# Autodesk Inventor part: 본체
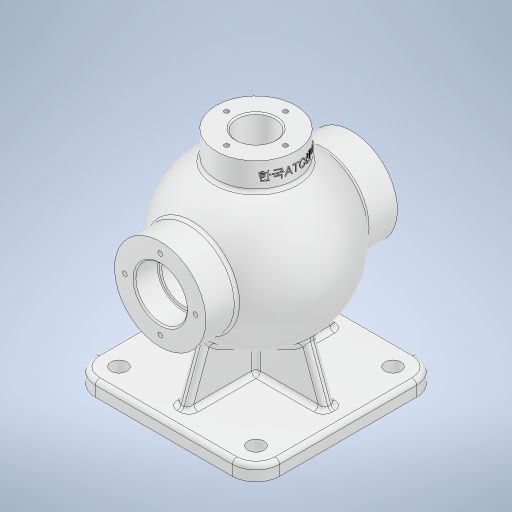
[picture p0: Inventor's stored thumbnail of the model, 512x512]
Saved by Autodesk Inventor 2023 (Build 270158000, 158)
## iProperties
Created: 2023-07
Part Number: 본체
Material: 알루미늄 6061
Document SubType Name: Modeling
Designer: Owner
Density: 2.7 g/cm^3
Appearance: 알루미늄 - 평지
Mass: 1526.72 g
Surface Area: 1173.82 cm^2
Volume: 565.453 cm^3
Author: Owner
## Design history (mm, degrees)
sketch "스케치1"
  geometry: L1 (62.5, 62.5)-(-62.5, 62.5); L2 (-62.5, 62.5)-(-62.5, -62.5); L3 (-62.5, -62.5)-(62.5, -62.5); L4 (62.5, -62.5)-(62.5, 62.5); L5 (62.5, 62.5)-(-62.5, -62.5); L6 (-62.5, 62.5)-(62.5, -62.5); 1 further point
  constraints: 12 end point, 2 midpoint, 2 parallel, 1 horizontal, 1 perpendicular
  dimensions: "d0" = 125 distance of L3.end L2.end; "d1" = 125 distance of L2.end L1.end
extrude "돌출1" new body sketch "스케치1" distance "d2" = 10; taper "d3" = 0 deg
sketch "스케치2"
  geometry: L1 (85, 65)-(85, -65); L2 (0, -62.5)-(0, 62.5) reference; L3 (85, 65)-(54, 65); L4 (54, -65)-(85, -65); L5 (54, 65)-(54, 44.215); L6 (54, -44.215)-(54, -65); A1 r 54 centre (85, 0) between (54, 44.215) and (54, -44.215); 8 further points
  constraints: 10 end point, 4 horizontal alignment, 3 vertical, 2 horizontal, 2 midpoint, 2 point on circle, 1 centre point, 1 coincident, 1 collinear, 6 other
  dimensions: "d5" = 85 distance between parallel lines of L2 L1; "d8" = 130 distance between parallel lines of L4 L3; "d11" = 31 distance of L1.start L3.end; "d12" = 54 radius of A1
revolve "회전1" sketch "스케치2" stored, may be unused: angle "d13" = 90 deg
sketch "스케치3"
  geometry: L1 (10, 50.5)-(85, 23.202); L2 (85, 23.202)-(85, -23.202); L3 (85, -23.202)-(10, -50.5); L4 (10, -62.5)-(10, 62.5) reference; L5 (0, -62.5)-(0, 62.5) reference; L6 (0, -62.5)-(10, -62.5) reference; L7 (0, 62.5)-(10, 62.5) reference; 1 further point
  constraints: 6 end point, 2 point on line, 1 vertical
  dimensions: "d14" = 12 distance from line of L6 L3.end; "d15" = 20 deg angle of L6 L3; "d16" = 12 distance from line of L7 L1.start; "d17" = 20 deg angle of L7 L1; "d18" = 85 distance between parallel lines of L5 L2
extrude "돌출2" join sketch "스케치3" stored distance "d19" = 8; taper "d20" = 0 deg
sketch "스케치4"
  geometry: L1 (62.5, 10)-(-62.5, 10) reference; L2 (62.5, 0)-(62.5, 10) reference; L3 (-62.5, 0)-(-62.5, 10) reference; L4 (-39.65, 39.811)-(-50.5, 10); L5 (-62.5, 10)-(62.5, 10) reference; A1 r 54 centre (0, 85) between (4, 31.148) and (-4, 31.148) reference; 1 further point
  constraints: 2 end point, 1 point on line
  dimensions: "d25" = 12 distance from line of L3 L4.end; "d26" = 20 deg angle of L3 L4
feature "리브1" sketch "스케치4" dims "d27" = 1, "d28" = 8, "d29" = 0, "d30" = 0, "d31" = 1, "d32" = 1
sketch "스케치5"
  geometry: L1 (54, 65)-(116, 65) reference; L2 (85, 65)-(85, -65); L3 (54, -65)-(116, -65) reference; A1 r 44 centre (85, 0) between (85, -44) and (85, 44); 1 further point
  constraints: 3 midpoint, 2 end point, 2 point on circle, 2 point on line, 1 centre point
  dimensions: "d33" = 88 diameter of A1
revolve "회전2" sketch "스케치5" stored, may be unused: angle "d34" = 90 deg
sketch "스케치6"
  geometry: C1 r 31 at (0, 0) reference; C2 r 17.5 at (0, 0); 1 further point
  constraints: 1 centre point, 1 coincident
  dimensions: "d35" = 35 diameter of C2
extrude "돌출3" cut sketch "스케치6" distance "d36" = 16; taper "d37" = 0 deg
sketch "스케치7"
  geometry: C1 r 17.5 at (0, 0) reference; C2 r 15 at (0, 0); 1 further point
  constraints: 1 centre point, 1 coincident
  dimensions: "d38" = 30 diameter of C2
extrude "돌출4" cut sketch "스케치7" stored distance "d39" = 10; taper "d40" = 0 deg
node "작업 평면1"
sketch "스케치8"
  geometry: C1 r 27 at (0, 0); 1 further point
  constraints: 1 centre point, 1 coincident
  dimensions: "d42" = 54 diameter of C1
extrude "돌출5" join sketch "스케치8" stored distance "d43" = 10; taper "d44" = 0 deg
sketch "스케치9"
  geometry: C1 r 27 at (0, 0) reference; C2 r 13 at (0, 0)
  constraints: 1 centre point, 1 coincident
  dimensions: "d45" = 26 diameter of C2
extrude "돌출6" cut sketch "스케치9" stored distance "d46" = 10; taper "d47" = 0 deg
sketch "스케치10"
  geometry: L1 (-62.5, -85)-(62.5, -85) reference; C1 r 17.5 at (0, 0) reference; 2 further points
  dimensions: "d48" = 85 distance from line of L1 point (-24, 0); "d49" = 24 distance of C1.centre point (-24, 0)
hole "구멍1" sketch "스케치10" at (-24, 0) diameter "d50" = 3.242; stored, may be unused: countersink angle "d54" = 90 deg, drill point angle "d56" = 118 deg; dims "d51" = 12, "d52" = 4, "d53" = 2, "d55" = 15
sketch "스케치11"
  geometry: C1 r 13 at (0, 0) reference; 1 further point
  constraints: 1 vertical alignment
  dimensions: "d60" = 20 distance of C1.centre point (0, -20)
hole "구멍2" sketch "스케치11" at (0, -20) diameter "d61" = 3.242; stored, may be unused: countersink angle "d65" = 90 deg, drill point angle "d67" = 118 deg; dims "d62" = 9, "d63" = 4, "d64" = 2, "d66" = 11
fillet "모깎기1" dims "d71" = 3
fillet "모깎기2" dims "d72" = 3
fillet "모깎기3" dims "d73" = 3
fillet "모깎기4" dims "d74" = 3
chamfer "모따기1" distance "d75" = 1; stored, may be unused: second distance "d76" = 2, angle "d77" = 45 deg
fillet "모깎기5" dims "d78" = 16
fillet "모깎기6" dims "d79" = 3
sketch "스케치12"
  geometry: C1 r 5.5 at (-46.5, 46.5); A1 r 13 centre (-46.5, 46.5) between (-46.5, 59.5) and (-59.5, 46.5) reference; 1 further point
  constraints: 1 centre point, 1 coincident
  dimensions: "d80" = 11 diameter of C1
extrude "돌출7" cut sketch "스케치12" extent not by distance; stored distance "d81" = 0; taper "d82" = 0 deg
node "작업 평면2"
sketch "스케치13"
  geometry: L1 (0, -27)-(0, 27) reference; L2 (-150, 46.5)-(-150, -46.5) reference; 3 further points
  constraints: 1 horizontal alignment, 1 midpoint, 1 other
  dimensions: "d83" = 9 distance from line of L1 point (-9, 0)
feature "엠보싱1" sketch "스케치13" dims "d0" = 125, "d1" = 125, "d84" = 0.5, "d85" = 0
fillet "모깎기7" dims "d86" = 0.6
node "솔리드1"
mirror "미러1"
mirror "미러2"
pattern_circular "원형 패턴1" dims angle "d58" = 360 deg
mirror "미러3"
pattern_circular "원형 패턴2" dims angle "d69" = 360 deg
mirror "미러4"
mirror "미러5"
feature "A9D066F2-1C7D-4E18-AEED-F7BC21143FA4" dims "d50" = 3.242, "d51" = 12, "d52" = 4, "d53" = 2, "d54" = 90 deg, "d55" = 15, "d56" = 118 deg
